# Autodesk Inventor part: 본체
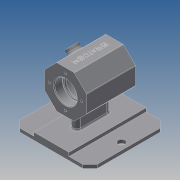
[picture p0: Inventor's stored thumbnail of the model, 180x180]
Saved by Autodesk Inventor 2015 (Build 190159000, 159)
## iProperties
Created: 2018-06
Part Number: 본체
Material: 일반
Document SubType Name: Modeling
Designer: 김영신
Density: 1 g/cm^3
Appearance: 기본값
Author: 김영신
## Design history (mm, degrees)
sketch "스케치1"
  geometry: L1 (-55, 55)-(55, 55); L2 (55, 55)-(55, -55); L3 (55, -55)-(-55, -55); L4 (-55, -55)-(-55, 55); 3 further points
  constraints: 8 end point, 2 midpoint, 2 parallel, 1 horizontal, 1 horizontal alignment, 1 perpendicular, 1 vertical alignment
  dimensions: "d0" = 110 distance between parallel lines of L2 L4; "d1" = 110 distance between parallel lines of L3 L1
extrude "돌출1" new body sketch "스케치1" distance "d2" = 5; taper "d3" = 0 deg
sketch "스케치2"
  geometry: L1 (-25, 55)-(25, 55); L2 (25, 55)-(25, -55); L3 (25, -55)-(-25, -55); L4 (-25, -55)-(-25, 55); L5 (55, 55)-(-55, 55) reference; L6 (55, -55)-(55, 55) reference; L7 (-55, 55)-(-55, -55) reference; 3 further points
  constraints: 8 end point, 2 midpoint, 2 parallel, 1 collinear, 1 horizontal, 1 horizontal alignment, 1 perpendicular, 1 vertical alignment
  dimensions: "d4" = 30 distance between parallel lines of L6 L2; "d5" = 30 distance between parallel lines of L7 L4 (derived)
extrude "돌출2" join sketch "스케치2" distance "d6" = 5; taper "d7" = 0 deg
sketch "스케치4"
  geometry: L1 (30, 74.426)-(30, 49.574); L2 (30, 49.574)-(12.426, 32); L3 (12.426, 32)-(-12.426, 32); L4 (-12.426, 32)-(-30, 49.574); L5 (-30, 49.574)-(-30, 74.426); L6 (-30, 74.426)-(-12.426, 92); L7 (-12.426, 92)-(12.426, 92); L8 (12.426, 92)-(30, 74.426); L9 (0, 62)-(12.426, 92); L10 (0, 62)-(-12.426, 92); L11 (0, 62)-(0, 92); C1 r 30 at (0, 62); 1 further point
  constraints: 22 end point, 2 vertical alignment, 1 centre point, 1 coincident, 1 midpoint, 1 vertical, 17 other
  dimensions: "d10" = 60 diameter of C1; "d11" = 62 distance of point (0, 0) C1.centre; "d12" = 22.5 deg angle of L9 L11 (derived); "d100" = 30 distance from line of C1.centre L5
extrude "돌출3" join sketch "스케치4" stored distance "d14" = 70; taper "d15" = 0 deg
sketch "스케치5"
  geometry: L1 (0, -19)-(0, 19); L2 (5, -19)-(5, 19); L3 (-5, 19)-(-5, -19); A1 r 5 centre (0, -19) between (-5, -19) and (5, -19); A2 r 5 centre (0, 19) between (5, 19) and (-5, 19); 2 further points
  constraints: 8 end point, 4 point on circle, 4 tangent, 2 centre point, 1 coincident, 1 midpoint, 1 parallel, 1 vertical
  dimensions: "d16" = 38 distance of L1.end L1.start; "d17" = 5 radius of A1
extrude "돌출4" join sketch "스케치5" stored distance "d18" = 70; taper "d19" = 0 deg
sketch "스케치8"
  geometry: L1 (-24.853, 70)-(0, 70) reference; C1 r 8 at (-12.426, 35); 2 further points
  constraints: 1 centre point, 1 horizontal alignment, 1 midpoint, 1 vertical alignment
  dimensions: "d30" = 16 diameter of C1
extrude "돌출5" join sketch "스케치8" distance "d31" = 7; taper "d32" = 0 deg
sketch "스케치9"
  geometry: L1 (-55, -55)-(-55, 55) reference; L2 (55, 55)-(55, -55) reference; C1 r 5 at (45, 0); C2 r 5 at (-45, 0); 1 further point
  constraints: 2 centre point, 2 horizontal alignment
  dimensions: "d33" = 10 diameter of C1; "d34" = 10 diameter of C2; "d35" = 10 distance from line of L1 C2.centre; "d36" = 10 distance from line of L2 C1.centre
extrude "돌출6" cut sketch "스케치9" stored distance "d37" = 7; taper "d38" = 0 deg
sketch "스케치10"
  geometry: L1 (35, 92)-(35, 74.426) reference; L2 (-35, 49.574)-(-35, 74.426) reference; L3 (35, 62)-(-35, 62); L4 (23, 76)-(20, 76); L5 (20, 76)-(20, 84); L6 (17, 87)-(-17, 87); L7 (-20, 84)-(-20, 76); L8 (-20, 76)-(-23, 76); L9 (-23, 76)-(-23, 77.7); L10 (-23.3, 78)-(-35, 78); L11 (-35, 78)-(-35, 62); L12 (35, 62)-(35, 78); L13 (35, 78)-(23.3, 78); L14 (23, 77.7)-(23, 76); A1 r 0.3 centre (23.3, 77.7) between (23.3, 78) and (23, 77.7); A2 r 0.3 centre (-23.3, 77.7) between (-23, 77.7) and (-23.3, 78); A3 r 3 centre (-17, 84) between (-17, 87) and (-20, 84); A4 r 3 centre (17, 84) between (20, 84) and (17, 87); 2 further points
  constraints: 24 end point, 8 perpendicular, 8 point on circle, 8 tangent, 4 centre point, 2 equal radius, 2 midpoint, 1 collinear, 1 horizontal, 1 point on line, 1 vertical alignment
  dimensions: "d39" = 62 distance from line of point (0, 0) L3; "d40" = 32 diameter of L13 L3; "d41" = 28 diameter of L4 L3; "d42" = 50 diameter of L6 L3; "d43" = 28 diameter of L8 L3; "d44" = 32 diameter of L10 L3; "d45" = 12 distance between parallel lines of L1 L14; "d46" = 3 distance between parallel lines of L5 L14; "d47" = 40 distance between parallel lines of L7 L5; "d48" = 3 distance between parallel lines of L9 L7; "d49" = 12 distance between parallel lines of L11 L9 (derived); "d50" = 0.3 radius of A1; "d51" = 3 radius of A3
revolve "회전1" sketch "스케치10" stored, may be unused: angle "d52" = 90 deg
chamfer "모따기1" distance "d53" = 1; stored, may be unused: second distance "d54" = 2, angle "d55" = 45 deg
sketch "스케치11" dims "d56" = 46
  geometry: C1 r 17 at (0, -62) reference; 3 further points
  constraints: 2 vertical alignment, 1 coincident, 2 other
hole "구멍1" sketch "스케치11" at (0, -85) diameter "d57" = 3.242; stored, may be unused: countersink angle "d61" = 90 deg, drill point angle "d63" = 118 deg; dims "d58" = 8, "d59" = 4, "d60" = 2, "d62" = 10
sketch "스케치12" dims "d67" = 46
  geometry: C1 r 17 at (0, 62) reference; 3 further points
  constraints: 2 vertical alignment, 1 coincident, 2 other
hole "구멍2" sketch "스케치12" at (0, 85) diameter "d68" = 3.242; stored, may be unused: countersink angle "d72" = 90 deg, drill point angle "d74" = 118 deg; dims "d69" = 8, "d70" = 4, "d71" = 2, "d73" = 10
hole "구멍3" diameter "d80" = 8; stored, may be unused: countersink angle "d84" = 90 deg, drill point angle "d86" = 118 deg; dims "d78" = 10, "d79" = 10, "d81" = 8, "d82" = 4, "d83" = 2, "d85" = 30
chamfer "모따기2" distance "d87" = 1; stored, may be unused: second distance "d88" = 2, angle "d89" = 45 deg
chamfer "모따기3" distance "d90" = 10; stored, may be unused: second distance "d91" = 2, angle "d92" = 45 deg
sketch "스케치13"
  geometry: L1 (0, 0)-(24.853, 0) reference; 2 further points
  constraints: 1 coincident, 1 other
  dimensions: "d93" = 35 distance from line of L1 point (12.426, -35)
feature "엠보싱1" sketch "스케치13" dims "d0" = 110, "d1" = 110, "d10" = 60, "d11" = 62, "d12" = 22.5 deg (derived), "d94" = 0.5, "d95" = 0, "d100" = 30
fillet "모깎기1" dims "d96" = 2
fillet "모깎기2" dims "d97" = 3
fillet "모깎기3" dims "d98" = 1
node "솔리드1"
pattern_circular "원형 패턴1" dims angle "d65" = 360 deg
pattern_circular "원형 패턴2" dims angle "d76" = 360 deg
